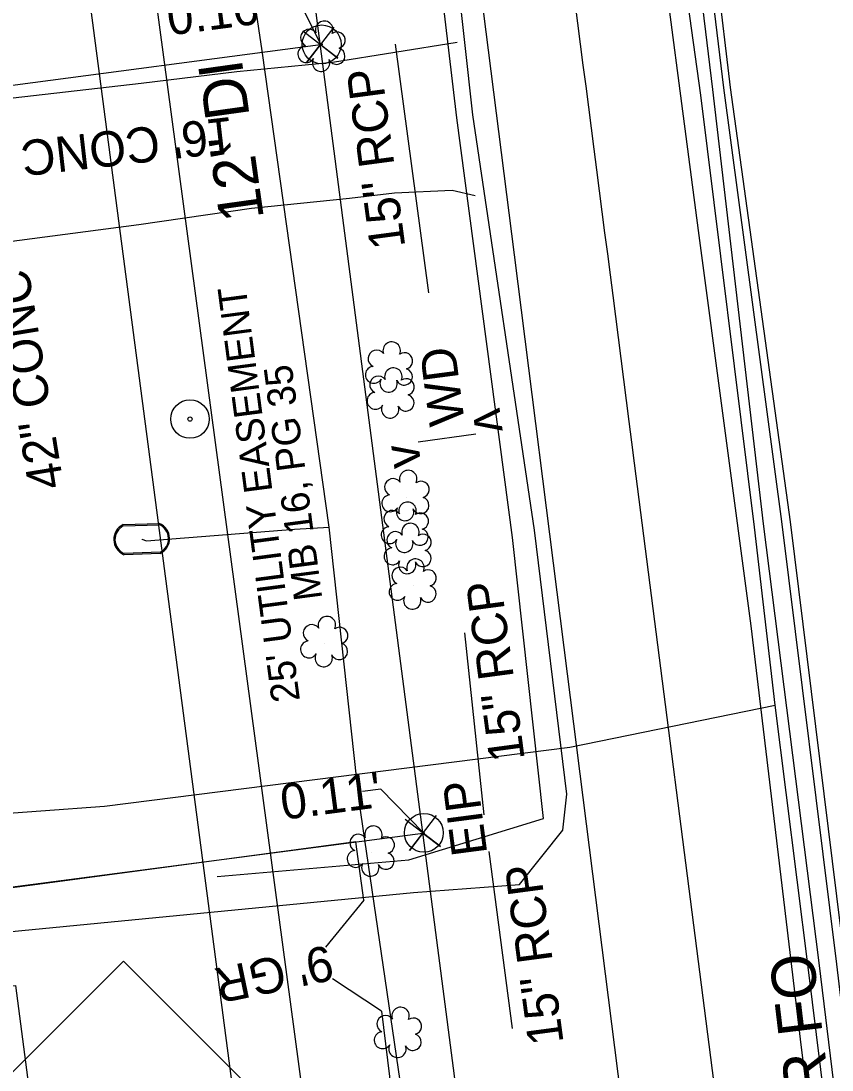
# Model space of a CAD drawing. Extents: x 2364404 to 2371833, y 798876 to 809754.
# Drawn here: x 2368367.6 to 2368459.4, y 807455.3 to 807574.1 of the extents above; entities that cross this region are included whole.
import ezdxf

# ---------------------------------------------------------------- set-up
doc = ezdxf.new("R2010")
doc.units = 0
for name, color, linetype in [('CTL Supplemental Horizontal and Vertical CELL', 7, 'Continuous'), ('Exist Building', 7, 'Continuous'), ('Exist Other Culture Area Outline Text', 7, 'Continuous'), ('Exist Other Culture Fence Line', 7, 'Continuous'), ('Exist Other Culture Gate', 7, 'Continuous'), ('Exist Other Culture Located Object CELL', 7, 'Continuous'), ('Exist Property Corner CELL', 7, 'Continuous'), ('Exist Property Iron Pin CELL', 7, 'Continuous'), ('Exist Property Iron Pin Text', 7, 'Continuous'), ('Exist Property Line', 7, 'Continuous'), ('Exist Property Line Leader', 7, 'Continuous'), ('Exist Property Line Text', 7, 'Continuous'), ('Exist Right of Way Easement Line', 7, 'Continuous'), ('Exist Right of Way Easement Line Text', 7, 'Continuous'), ('Exist Right of Way Line', 7, 'Continuous'), ('Exist Roads EOP', 7, 'Continuous'), ('Exist Roads EOP Other', 7, 'Continuous'), ('Exist Roads EOP Other Text', 7, 'Continuous'), ('Exist Roads Soil Text', 7, 'Continuous'), ('Exist Structure Minor Footbridge', 7, 'Continuous'), ('Exist Structure Minor Footbridge Terminator', 7, 'Continuous'), ('Exist Structure Minor Footbridge Text', 7, 'Continuous'), ('Exist Structure Minor Pipes RCP 15 Inch', 7, 'Continuous'), ('Exist Structure Minor Pipes RCP 15 Inch Text', 7, 'Continuous'), ('Exist Utilities Gas UG Line SUE LOS B', 7, 'Continuous'), ('Exist Utilities Sanitary Sewer UG Line', 7, 'Continuous'), ('Exist Utilities Telephone UG Cable SUE LOS C', 7, 'Continuous'), ('Exist Utilities Telephone UG FO SUE LOS B', 7, 'Continuous'), ('Exist Utilities Telephone UG FO SUE LOS B Text', 7, 'Continuous'), ('Exist Utilities Telephone UG FO SUE LOS D', 7, 'Continuous'), ('Exist Utilities Water Meter CELL', 7, 'Continuous'), ('Exist Utilities Water UG Line SUE LOS B', 7, 'Continuous'), ('Exist Utilities Water UG Line SUE LOS B Text', 7, 'Continuous'), ('Exist Vegetation Shrub CELL', 7, 'Continuous'), ('Prop Horizontal Alignment', 7, 'Continuous')]:
    doc.layers.add(name, color=color, linetype=linetype)

msp = doc.modelspace()

# ---------------------------------------------------------------- linework, layer by layer
at = {"layer": 'CTL Supplemental Horizontal and Vertical CELL'}
msp.add_lwpolyline([(2368312.4, 807400.83), (2368379.23, 807467.66), (2368446.17, 807400.72), (2368379.35, 807333.89)], close=True, dxfattribs=at)
at = {"layer": 'Exist Building'}
msp.add_lwpolyline([(2368366.97, 807464.89), (2368373.94, 807411.7), (2368344.89, 807407.89), (2368344.02, 807414.48), (2368340.29, 807413.99), (2368339.28, 807421.68), (2368342.85, 807422.14), (2368337.75, 807461.06)], close=True, dxfattribs=at)
at = {"layer": 'Exist Other Culture Fence Line'}
for points in [[(2368406.44, 807474.54), (2368405.51, 807481.15), (2368370.62, 807476.49), (2368333.09, 807471.52), (2368294.55, 807466.63)], [(2368408.43, 807462), (2368410.22, 807447.2), (2368414.77, 807413.48), (2368417.34, 807392.49), (2368374.59, 807386.82), (2368352.65, 807384.34), (2368342.56, 807382.91), (2368342.36, 807384.28), (2368321.98, 807381.07), (2368304.49, 807378.27), (2368301.17, 807377.76)]]:
    msp.add_lwpolyline(points, dxfattribs=at)
at = {"layer": 'Exist Other Culture Gate'}
for p, q in [((2368406.44, 807474.54), (2368402.1, 807469.25)), ((2368408.43, 807462), (2368402.86, 807465.66))]:
    msp.add_line(p, q, dxfattribs=at)
at = {"layer": 'Exist Other Culture Located Object CELL'}
for radius in [2.18, 0.24]:
    msp.add_circle((2368386.74, 807529.01), radius, dxfattribs=at)
at = {"layer": 'Exist Property Corner CELL'}
for p, q in [((2368401.5, 807571.4), (2368401.5, 807571.4)), ((2368413.11, 807482.15), (2368413.11, 807482.15))]:
    msp.add_line(p, q, dxfattribs=at)
for points in [[(2368403.02, 807573.38), (2368399.97, 807569.42), (2368401.5, 807571.4), (2368403.48, 807569.88), (2368399.51, 807572.92)], [(2368414.63, 807484.14), (2368411.58, 807480.17), (2368413.11, 807482.15), (2368415.09, 807480.63), (2368411.12, 807483.68)]]:
    msp.add_lwpolyline(points, dxfattribs=at)
at = {"layer": 'Exist Property Iron Pin CELL'}
for centre, radius in [((2368401.65, 807571.42), 2.2), ((2368401.65, 807571.42), 0.0707), ((2368413.22, 807482.17), 2.2), ((2368413.22, 807482.17), 0.0707)]:
    msp.add_circle(centre, radius, dxfattribs=at)
at = {"layer": 'Exist Property Line'}
for p, q in [((2368235.72, 807549.63), (2368401.5, 807571.4)), ((2368401.5, 807571.4), (2368401.65, 807571.42)), ((2368247.44, 807460.4), (2368413.11, 807482.15)), ((2368413.11, 807482.15), (2368413.22, 807482.17))]:
    msp.add_line(p, q, dxfattribs=at)
at = {"layer": 'Exist Property Line Leader'}
for points in [[(2368401.57, 807571.41), (2368399.07, 807576.42), (2368395.68, 807575.93)], [(2368413.16, 807482.16), (2368408.36, 807487.12), (2368406.29, 807486.85)]]:
    msp.add_lwpolyline(points, dxfattribs=at)
at = {"layer": 'Exist Right of Way Easement Line'}
msp.add_line((2368511.71, 806538.64), (2368344.2, 807814.14), dxfattribs=at)
at = {"layer": 'Exist Right of Way Line'}
msp.add_line((2368533.02, 806560.45), (2368368.2, 807827.36), dxfattribs=at)
at = {"layer": 'Exist Roads EOP'}
for points in [[(2368458.85, 807273.24), (2368452.4, 807323.88), (2368446.15, 807368.12), (2368444.02, 807369.35), (2368441.6, 807369.34), (2368439.16, 807392.12), (2368442.82, 807396.21), (2368435.2, 807454.89), (2368429.11, 807503.15), (2368423.49, 807547.61), (2368418.51, 807586.84), (2368409.79, 807654.27), (2368402.88, 807704.72), (2368396.58, 807752.35), (2368389.7, 807800.7), (2368383.01, 807844.61), (2368373.21, 807897.74)], [(2368479.96, 807275.52), (2368472.82, 807329.17), (2368467.3, 807372.73), (2368463.49, 807399.04), (2368455.99, 807457.89), (2368450.28, 807505.61), (2368444.32, 807550.36), (2368439.14, 807589.77), (2368430.88, 807657.09), (2368424.4, 807706.96), (2368418, 807755.78), (2368415.07, 807804.32), (2368408.4, 807848.6), (2368404.75, 807897.99)]]:
    msp.add_lwpolyline(points, dxfattribs=at)
at = {"layer": 'Exist Roads EOP Other'}
msp.add_line((2368416.99, 807571.65), (2368402.89, 807569.36), dxfattribs=at)
for points in [[(2368402.89, 807569.36), (2368392.04, 807568.3), (2368381.2, 807566.99), (2368360.42, 807564.6), (2368347.48, 807563.08), (2368346.74, 807562.98)], [(2368419.04, 807554.27), (2368416.41, 807554.9), (2368409.89, 807554.57), (2368404.81, 807553.96), (2368393.72, 807552.85), (2368380.94, 807550.99), (2368362.81, 807548.61)]]:
    msp.add_lwpolyline(points, dxfattribs=at)
at = {"layer": 'Exist Structure Minor Footbridge'}
msp.add_line((2368419.09, 807527.29), (2368412.58, 807526.38), dxfattribs=at)
at = {"layer": 'Exist Structure Minor Pipes RCP 15 Inch'}
for p, q in [((2368409.97, 807571.45), (2368413.73, 807543.29)), ((2368417.82, 807504.81), (2368420.01, 807484.21)), ((2368420.56, 807480.06), (2368423.2, 807460.04))]:
    msp.add_line(p, q, dxfattribs=at)
at = {"layer": 'Exist Utilities Gas UG Line SUE LOS B'}
for points in [[(2368482.33, 807269.18), (2368476.59, 807310.66), (2368475.28, 807318.93), (2368469.46, 807367.86), (2368462.89, 807417.28), (2368456.74, 807466.98), (2368452.98, 807496.64), (2368450.66, 807516.79), (2368444.57, 807565.67), (2368442.07, 807583.58), (2368437.6, 807615.09), (2368434.95, 807636.28), (2368430.96, 807664.36), (2368426.87, 807696.93), (2368423.49, 807727.61), (2368418.1, 807767.6), (2368413.6, 807813.99), (2368409, 807861.86), (2368407.26, 807895.83), (2368407.32, 807898.29), (2368407.49, 807900.26)], [(2368313, 807431.3), (2368315.43, 807441.24), (2368326.34, 807463.56), (2368329.2, 807470.06), (2368362.61, 807484.12), (2368377.08, 807485.2), (2368429.76, 807491.87), (2368452.98, 807496.64)]]:
    msp.add_lwpolyline(points, dxfattribs=at)
at = {"layer": 'Exist Utilities Sanitary Sewer UG Line'}
msp.add_line((2368403.25, 807424.76), (2368350.71, 807816.86), dxfattribs=at)
at = {"layer": 'Exist Utilities Telephone UG Cable SUE LOS C'}
for points in [[(2368389.8, 807477.23), (2368411.52, 807479.13), (2368426.75, 807483.79), (2368423.25, 807515.6), (2368416.95, 807563.1), (2368411.16, 807611.97), (2368408.13, 807633.66), (2368404.45, 807661.14), (2368400.96, 807692.3), (2368397.77, 807710.8), (2368392.17, 807754.58), (2368386.02, 807810.85), (2368379.04, 807858.46), (2368375.16, 807879.37), (2368367.44, 807903.09), (2368362.27, 807911.13), (2368354.75, 807913.38)], [(2368485.62, 807270.73), (2368476.5, 807319.29), (2368470.88, 807368.16), (2368464.04, 807417.61), (2368457.98, 807467.45), (2368451.69, 807517.15), (2368445.92, 807566.33), (2368439.92, 807615.73), (2368432.72, 807664.72), (2368430.11, 807698.46), (2368431.5, 807700.65), (2368440.15, 807701.7), (2368446.87, 807703.63), (2368447.34, 807703.99)], [(2368364.95, 807470.85), (2368412.03, 807475.41), (2368424.04, 807476.34), (2368428.94, 807482.47), (2368429.41, 807486.55), (2368425.74, 807516.43), (2368418.77, 807563.45), (2368413.38, 807612.29), (2368409.9, 807634.21), (2368405.63, 807637.87), (2368398.67, 807639.34), (2368392.73, 807633.04), (2368391.83, 807625.63), (2368393.11, 807623.54)]]:
    msp.add_lwpolyline(points, dxfattribs=at)
at = {"layer": 'Exist Utilities Telephone UG FO SUE LOS B'}
msp.add_lwpolyline([(2368483.26, 807270.12), (2368478.16, 807319.19), (2368472.6, 807368.27), (2368465.88, 807417.7), (2368459.97, 807467.31), (2368453.73, 807517.43), (2368447.2, 807566.5), (2368441.17, 807616.03), (2368437.86, 807642.28), (2368439.4, 807645.03), (2368464.67, 807649.93), (2368491.27, 807657.09), (2368500.07, 807662.02), (2368501.11, 807664.27), (2368501.15, 807666.19)], dxfattribs=at)
at = {"layer": 'Exist Utilities Telephone UG FO SUE LOS D'}
msp.add_lwpolyline([(2368484.81, 807270.66), (2368473.51, 807368.34), (2368466.85, 807417.95), (2368460.93, 807467.4), (2368454.73, 807517.39), (2368447.92, 807566.55), (2368442.04, 807616.09), (2368438.78, 807642.11), (2368440.24, 807644.29), (2368465.47, 807648.69), (2368492.11, 807655.82), (2368501.13, 807661.53), (2368502.06, 807664.41), (2368502.38, 807666.35)], dxfattribs=at)
at = {"layer": 'Exist Utilities Water Meter CELL'}
msp.add_line((2368381.28, 807515.43), (2368381.28, 807515.43), dxfattribs=at)
for points in [[(2368379.18, 807517.06), (2368383.26, 807517.19)], [(2368379.19, 807516.92), (2368383.26, 807517.05)], [(2368383.36, 807513.93), (2368379.27, 807513.8)], [(2368383.37, 807513.79), (2368379.27, 807513.66)]]:
    msp.add_lwpolyline(points, dxfattribs=at)
for centre, radius, start, end in [((2368379.97, 807515.38), 1.86, 115.0467, 247.848), ((2368379.98, 807515.38), 1.73, 117.1696, 245.651), ((2368382.57, 807515.47), 1.86, 295.517, 68.177), ((2368382.58, 807515.47), 1.73, 296.9958, 66.7415)]:
    msp.add_arc(centre, radius, start, end, dxfattribs=at)
at = {"layer": 'Exist Utilities Water UG Line SUE LOS B'}
for points in [[(2368435.61, 807263.12), (2368428.93, 807315.03), (2368426.08, 807333.8), (2368421.96, 807363.83), (2368414.11, 807429.65), (2368405.9, 807485.75), (2368402.48, 807516.76), (2368394.93, 807570.69), (2368390.68, 807599.07), (2368390.12, 807605.12), (2368383.55, 807658.17), (2368377.22, 807707.96), (2368370.41, 807753.28)], [(2368381.28, 807515.43), (2368381.82, 807515.21), (2368398.56, 807516.56), (2368402.48, 807516.76)]]:
    msp.add_lwpolyline(points, dxfattribs=at)
at = {"layer": 'Exist Vegetation Shrub CELL'}
for p, q in [((2368401.71, 807571.03), (2368401.71, 807571.03)), ((2368409.35, 807534.72), (2368409.35, 807534.72)), ((2368409.54, 807531.78), (2368409.54, 807531.78)), ((2368411.22, 807520.17), (2368411.22, 807520.17)), ((2368411.14, 807516.59), (2368411.14, 807516.59)), ((2368411.47, 807514.18), (2368411.47, 807514.18)), ((2368412.04, 807510.15), (2368412.04, 807510.15)), ((2368402.01, 807503.64), (2368402.01, 807503.64)), ((2368407.29, 807479.92), (2368407.29, 807479.92)), ((2368410.35, 807459.41), (2368410.35, 807459.41))]:
    msp.add_line(p, q, dxfattribs=at)
for centre, radius, start, end in [((2368401.94, 807573.07), 0.99, 334.8391, 200.4717), ((2368400.23, 807572.16), 0.968, 35.8908, 245.4216), ((2368403.38, 807571.9), 0.929, 284.4567, 126.0861), ((2368399.91, 807570.32), 0.955, 95.1099, 327.9534), ((2368403.35, 807570.1), 0.937, 204.9913, 73.4601), ((2368401.58, 807569.34), 0.984, 151.2797, 21.387), ((2368409.58, 807536.76), 0.99, 334.8391, 200.4717), ((2368407.87, 807535.85), 0.968, 35.8908, 245.4216), ((2368411.03, 807535.59), 0.929, 284.4567, 126.0861), ((2368407.55, 807534.02), 0.955, 95.1099, 327.9534), ((2368409.77, 807533.82), 0.99, 334.8391, 200.4717), ((2368410.99, 807533.79), 0.937, 204.9913, 73.4601), ((2368408.06, 807532.91), 0.968, 35.8908, 245.4216), ((2368409.23, 807533.04), 0.984, 151.2797, 21.387), ((2368411.21, 807532.65), 0.929, 284.4567, 126.0861), ((2368407.74, 807531.08), 0.955, 95.1099, 327.9534), ((2368411.18, 807530.85), 0.937, 204.9913, 73.4601), ((2368409.41, 807530.1), 0.984, 151.2797, 21.387), ((2368409.74, 807521.3), 0.968, 35.8908, 245.4216), ((2368411.45, 807522.22), 0.99, 334.8391, 200.4717), ((2368412.89, 807521.04), 0.929, 284.4567, 126.0861), ((2368409.42, 807519.47), 0.955, 95.1099, 327.9534), ((2368412.86, 807519.25), 0.937, 204.9913, 73.4601), ((2368409.66, 807517.71), 0.968, 35.8908, 245.4216), ((2368411.09, 807518.49), 0.984, 151.2797, 21.387), ((2368411.37, 807518.63), 0.99, 334.8391, 200.4717), ((2368412.81, 807517.45), 0.929, 284.4567, 126.0861), ((2368409.34, 807515.88), 0.955, 95.1099, 327.9534), ((2368409.99, 807515.3), 0.968, 35.8908, 245.4216), ((2368411.7, 807516.22), 0.99, 334.8391, 200.4717), ((2368412.78, 807515.66), 0.937, 204.9913, 73.4601), ((2368411.01, 807514.9), 0.984, 151.2797, 21.387), ((2368413.14, 807515.05), 0.929, 284.4567, 126.0861), ((2368409.67, 807513.47), 0.955, 95.1099, 327.9534), ((2368413.11, 807513.25), 0.937, 204.9913, 73.4601), ((2368411.34, 807512.49), 0.984, 151.2797, 21.387), ((2368412.27, 807512.19), 0.99, 334.8391, 200.4717), ((2368410.56, 807511.28), 0.968, 35.8908, 245.4216), ((2368413.71, 807511.02), 0.929, 284.4567, 126.0861), ((2368410.24, 807509.45), 0.955, 95.1099, 327.9534), ((2368413.68, 807509.22), 0.937, 204.9913, 73.4601), ((2368411.91, 807508.47), 0.984, 151.2797, 21.387), ((2368402.24, 807505.68), 0.99, 334.8391, 200.4717), ((2368400.53, 807504.77), 0.968, 35.8908, 245.4216), ((2368403.68, 807504.51), 0.929, 284.4567, 126.0861), ((2368400.21, 807502.94), 0.955, 95.1099, 327.9534), ((2368403.65, 807502.72), 0.937, 204.9913, 73.4601), ((2368401.88, 807501.96), 0.984, 151.2797, 21.387), ((2368407.51, 807481.96), 0.99, 334.8391, 200.4717), ((2368405.8, 807481.05), 0.968, 35.8908, 245.4216), ((2368408.96, 807480.79), 0.929, 284.4567, 126.0861), ((2368405.49, 807479.22), 0.955, 95.1099, 327.9534), ((2368408.92, 807478.99), 0.937, 204.9913, 73.4601), ((2368407.16, 807478.24), 0.984, 151.2797, 21.387), ((2368410.58, 807461.45), 0.99, 334.8391, 200.4717), ((2368408.87, 807460.53), 0.968, 35.8908, 245.4216), ((2368412.03, 807460.28), 0.929, 284.4567, 126.0861), ((2368408.55, 807458.7), 0.955, 95.1099, 327.9534), ((2368411.99, 807458.48), 0.937, 204.9913, 73.4601), ((2368410.23, 807457.72), 0.984, 151.2797, 21.387)]:
    msp.add_arc(centre, radius, start, end, dxfattribs=at)
at = {"layer": 'Prop Horizontal Alignment'}
msp.add_line((2368515.76, 806910.55), (2368437.08, 807524), dxfattribs=at)
msp.add_arc((2328762.05, 802435.58), 40000, 7.308437, 7.418036, dxfattribs=at)

# ---------------------------------------------------------------- texts
at = {"layer": 'Exist Other Culture Area Outline Text'}
msp.add_text('42" CONC', height=4, rotation=99.2972, dxfattribs=at).set_placement((2368372.48, 807521.38))
at = {"layer": 'Exist Property Iron Pin Text'}
msp.add_text('EIP', height=4, rotation=97.4798, dxfattribs=at).set_placement((2368420.41, 807479.82))
at = {"layer": 'Exist Property Line Text'}
for s, p in [("0.16'", (2368384.4, 807572.42)), ("0.11'", (2368397.26, 807483.63))]:
    msp.add_text(s, height=4, rotation=7.4817, dxfattribs=at).set_placement(p)
at = {"layer": 'Exist Right of Way Easement Line Text'}
for s, p in [("25' UTILITY EASEMENT", (2368399.2, 807497.16)), ('MB 16, PG 35', (2368401.73, 807508.68))]:
    msp.add_text(s, height=3.2, rotation=97.4798, dxfattribs=at).set_placement(p)
at = {"layer": 'Exist Roads EOP Other Text'}
msp.add_text("16' CONC", height=4, rotation=186.5667, dxfattribs=at).set_placement((2368391.48, 807563.23))
at = {"layer": 'Exist Roads Soil Text'}
msp.add_text("9' GR", height=4, rotation=191.7625, dxfattribs=at).set_placement((2368402.46, 807469.5))
at = {"layer": 'Exist Structure Minor Footbridge Terminator'}
for rotation, p in [(277.9581, (2368418.73, 807529.91)), (97.9581, (2368412.94, 807523.76))]:
    msp.add_text('v', height=4, rotation=rotation, dxfattribs=at).set_placement(p)
at = {"layer": 'Exist Structure Minor Footbridge Text'}
msp.add_text('WD', height=4, rotation=97.4798, dxfattribs=at).set_placement((2368417.86, 807528.55))
at = {"layer": 'Exist Structure Minor Pipes RCP 15 Inch Text'}
for p in [(2368411.13, 807548.51), (2368424.65, 807490.5), (2368429.05, 807458.42)]:
    msp.add_text('15" RCP', height=4, rotation=97.5936, dxfattribs=at).set_placement(p)
at = {"layer": 'Exist Utilities Telephone UG FO SUE LOS B Text'}
msp.add_text('48 STR FO', height=5, rotation=96.8009, dxfattribs=at).set_placement((2368461.28, 807435.18))
at = {"layer": 'Exist Utilities Water UG Line SUE LOS B Text'}
msp.add_text('12" DI', height=5, rotation=97.9648, dxfattribs=at).set_placement((2368395.12, 807551.74))

doc.saveas('drawing.dxf')
